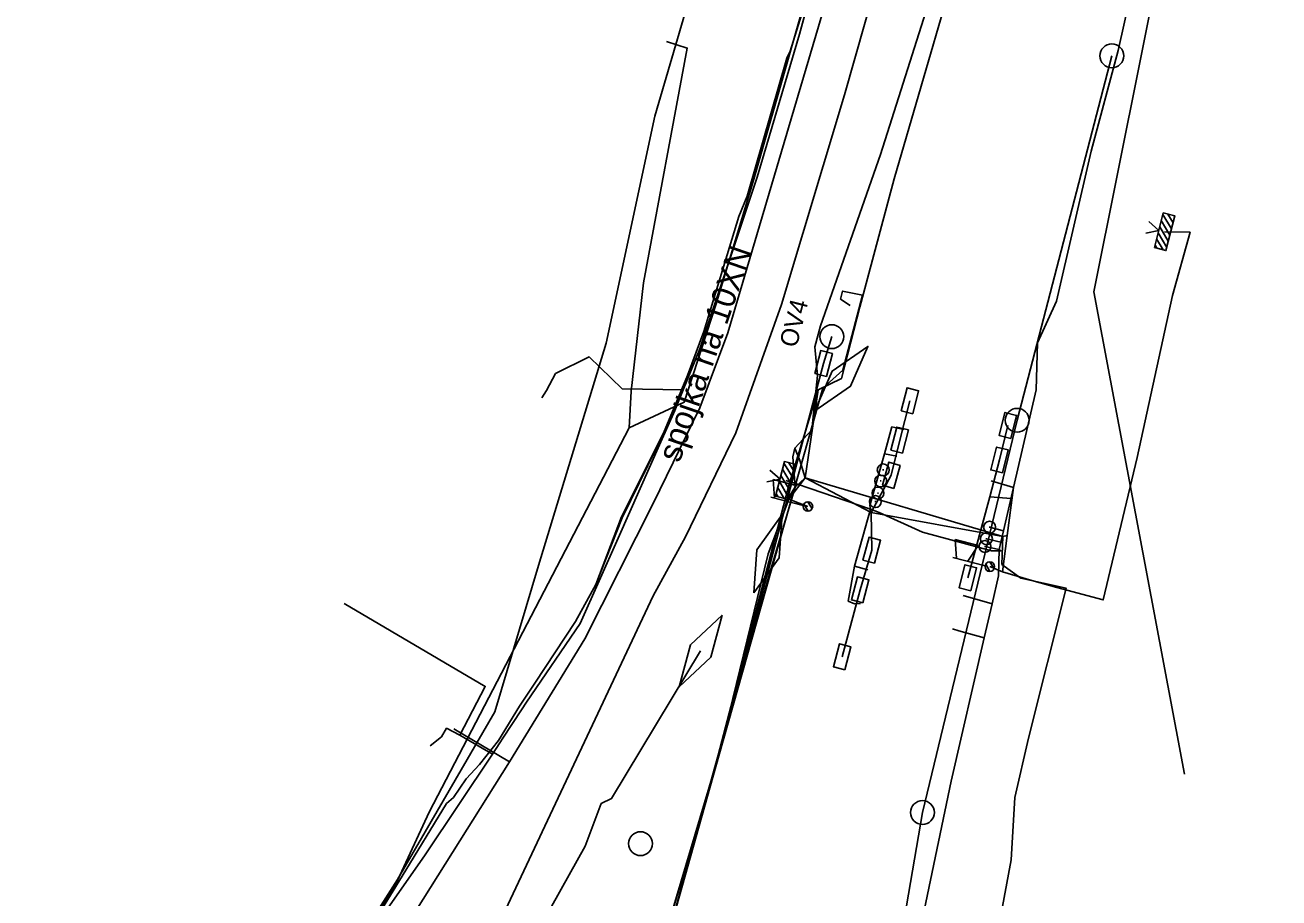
# Model space of a CAD drawing. Extents: x -748507 to -687366, y -1057342 to -1024924.
# Drawn here: x -743353.8 to -743248.5, y -1034654.5 to -1034581.2 of the extents above; entities that cross this region are included whole.
import ezdxf

# ---------------------------------------------------------------- set-up
doc = ezdxf.new("R2010")
doc.units = 0
for name, color, linetype in [('6kV - SŽDC', 7, 'Continuous'), ('DK + TKK - SŽDC', 7, 'Continuous'), ('kanalizace ČD', 7, 'Continuous'), ('PRE - NN', 7, 'Continuous'), ('PRE - OK', 7, 'Continuous'), ('PRE - VN', 7, 'Continuous'), ('Sděl MK - SŽDC', 7, 'Continuous'), ('STL - PRAŽSKÁ PLYNÁRENSKÁ', 7, 'Continuous'), ('Telefonica O2', 7, 'Continuous'), ('TK+DOK_Pha Holešovice - Kralupy', 7, 'Continuous'), ('Vedení NN - SŽDC', 7, 'Continuous')]:
    doc.layers.add(name, color=color, linetype=linetype)

msp = doc.modelspace()

# ---------------------------------------------------------------- linework, layer by layer
at = {"layer": '6kV - SŽDC'}
for points in [[(-743295.26, -1034630.77), (-743296.21, -1034634.29), (-743298.88, -1034636.77), (-743297.93, -1034633.25), (-743295.26, -1034630.77)], [(-743297.07, -1034633.77), (-743304.54, -1034646.16), (-743305.41, -1034646.57), (-743306.77, -1034650.16), (-743310.94, -1034657.62), (-743310.76, -1034659.86), (-743313.4, -1034662.22), (-743314.46, -1034662.46), (-743323.73, -1034678.74), (-743332.19, -1034693.38), (-743337.55, -1034703.39), (-743340.58, -1034715.43), (-743341.14, -1034718.66)]]:
    msp.add_lwpolyline(points, dxfattribs=at)
at = {"layer": 'DK + TKK - SŽDC'}
for p, q in [((-743289.34, -1034619.22), (-743290.07, -1034618.01)), ((-743289.21, -1034618.71), (-743289.65, -1034617.98)), ((-743289.08, -1034618.2), (-743289.13, -1034618.11)), ((-743289.61, -1034620.25), (-743290.33, -1034619.04)), ((-743289.47, -1034619.74), (-743290.2, -1034618.52)), ((-743282, -1034619.5), (-743281.9, -1034619.5)), ((-743281.79, -1034618.57), (-743281.69, -1034618.57)), ((-743290.05, -1034620.97), (-743290.59, -1034620.07)), ((-743289.74, -1034620.77), (-743290.46, -1034619.55)), ((-743282.23, -1034620.52), (-743282.13, -1034620.52)), ((-743290.57, -1034620.84), (-743290.72, -1034620.58)), ((-743282.45, -1034621.23), (-743282.35, -1034621.23)), ((-743272.86, -1034623.38), (-743272.76, -1034623.38)), ((-743273.13, -1034624.35), (-743273.03, -1034624.35)), ((-743273.25, -1034625), (-743273.15, -1034625))]:
    msp.add_line(p, q, dxfattribs=at)
for points in [[(-743285.25, -1034610.91), (-743283.7, -1034604.91), (-743280.81, -1034594.13), (-743276.29, -1034578.55), (-743273.28, -1034568.35), (-743270.77, -1034566.1), (-743268.13, -1034563.75), (-743265.78, -1034554.28)], [(-743262.02, -1034583.38), (-743259.96, -1034574.09), (-743257.39, -1034564.51)], [(-743268.89, -1034611.84), (-743268.78, -1034607.9), (-743267.19, -1034604.4), (-743264.3, -1034591.83), (-743262.02, -1034583.38)], [(-743295.6, -1034642.52), (-743289.66, -1034619.88), (-743287.21, -1034611.85), (-743285.25, -1034610.91)], [(-743270.8, -1034620.05), (-743268.89, -1034611.84)], [(-743271.04, -1034615.93), (-743272.01, -1034615.68), (-743271.52, -1034613.75), (-743270.55, -1034614), (-743271.04, -1034615.93)], [(-743281.63, -1034617.23), (-743281.01, -1034614.96)], [(-743281.01, -1034614.96), (-743280.01, -1034615.18)], [(-743272.79, -1034620.84), (-743271.98, -1034617.74), (-743271.28, -1034614.84)], [(-743282.8, -1034621.87), (-743282.87, -1034621.55), (-743281.63, -1034617.23), (-743280.59, -1034617.42)], [(-743271.74, -1034618.83), (-743272.71, -1034618.58), (-743272.22, -1034616.65), (-743271.25, -1034616.9), (-743271.74, -1034618.83)], [(-743290.78, -1034620.79), (-743290.03, -1034617.88), (-743289.06, -1034618.13), (-743289.81, -1034621.04), (-743290.78, -1034620.79)], [(-743291.5, -1034619.57), (-743290.4, -1034619.34), (-743291.25, -1034618.6)], [(-743289.09, -1034619.71), (-743289.92, -1034619.46)], [(-743288.28, -1034619.23), (-743271.7, -1034624.16)], [(-743270.8, -1034620.05), (-743272.67, -1034619.48)], [(-743282.8, -1034621.87), (-743286.9, -1034620.46), (-743287.78, -1034620.15), (-743289.09, -1034619.71)], [(-743272.6, -1034629.81), (-743272.06, -1034627.47), (-743272.01, -1034625.24), (-743271.87, -1034624.63), (-743271.65, -1034623.68), (-743270.8, -1034620.05)], [(-743274.64, -1034627.62), (-743272.79, -1034620.84), (-743270.99, -1034620.96)], [(-743282.8, -1034621.87), (-743284.14, -1034626.65), (-743283.02, -1034626.97)], [(-743278.43, -1034623.8), (-743282.08, -1034622.14), (-743282.8, -1034621.87)], [(-743271.65, -1034623.68), (-743272.81, -1034623.38)], [(-743272.01, -1034625.24), (-743271.86, -1034625.36), (-743272.64, -1034625.36), (-743278.43, -1034623.8)], [(-743271.87, -1034624.63), (-743273.08, -1034624.35)], [(-743272.01, -1034625.24), (-743273.2, -1034625)], [(-743284.14, -1034626.65), (-743284.69, -1034629.6)], [(-743274.4, -1034628.71), (-743275.37, -1034628.46), (-743274.88, -1034626.53), (-743273.91, -1034626.78), (-743274.4, -1034628.71)], [(-743284.69, -1034629.6), (-743284.16, -1034629.8), (-743283.64, -1034629.79)], [(-743273.26, -1034632.66), (-743272.6, -1034629.81), (-743275.04, -1034629.11)], [(-743276.03, -1034644.69), (-743273.26, -1034632.66), (-743275.38, -1034632.08), (-743275.92, -1034631.92)], [(-743315.44, -1034713.05), (-743314.23, -1034708.71), (-743313.63, -1034706.6), (-743302.64, -1034667.85), (-743295.6, -1034642.52)], [(-743287.3, -1034726.01), (-743282.01, -1034701.16), (-743281.85, -1034698.52), (-743280.62, -1034695.37), (-743278.88, -1034691.73), (-743277.32, -1034684.93), (-743277.88, -1034683.89), (-743280.38, -1034683), (-743283.09, -1034682.28), (-743283.91, -1034682.14), (-743283.65, -1034681.11), (-743283.36, -1034679.73), (-743281.64, -1034671.49), (-743276.03, -1034644.69)]]:
    msp.add_lwpolyline(points, dxfattribs=at)
msp.add_lwpolyline([(-743290.78, -1034620.79), (-743290.03, -1034617.88), (-743289.06, -1034618.13), (-743289.81, -1034621.04)], close=True, dxfattribs=at)
for centre in [(-743281.74, -1034618.57), (-743281.95, -1034619.5), (-743282.18, -1034620.52), (-743282.4, -1034621.23), (-743272.81, -1034623.38), (-743273.2, -1034625), (-743273.08, -1034624.35)]:
    msp.add_circle(centre, 0.5, dxfattribs=at)
at = {"layer": 'kanalizace ČD'}
msp.add_lwpolyline([(-743262.55, -1034583.82), (-743270.5, -1034614.41), (-743278.45, -1034647.33), (-743284.53, -1034682.91), (-743290.75, -1034695.35)], dxfattribs=at)
for centre in [(-743262.55, -1034583.82), (-743270.5, -1034614.41), (-743278.45, -1034647.33), (-743302.11, -1034649.94)]:
    msp.add_circle(centre, 1, dxfattribs=at)
at = {"layer": 'PRE - NN'}
for points in [[(-743303.07, -1034615.04), (-743298.46, -1034612.89), (-743295.78, -1034604.72), (-743292.59, -1034594.17), (-743286.55, -1034573.02), (-743286.07, -1034571.35), (-743285.82, -1034570.59), (-743284.5, -1034566.54)], [(-743299.92, -1034582.63), (-743298.19, -1034583.17), (-743301.86, -1034602.86), (-743302.89, -1034611.97), (-743303.07, -1034615.04)], [(-743373.22, -1034733.88), (-743372.79, -1034733.31), (-743370.86, -1034730.74), (-743367.71, -1034726.54), (-743355.34, -1034708.17), (-743347.28, -1034694.56), (-743327.35, -1034660.91), (-743322.5, -1034653.04), (-743319.86, -1034647.3), (-743303.07, -1034615.04)]]:
    msp.add_lwpolyline(points, dxfattribs=at)
at = {"layer": 'PRE - OK'}
msp.add_lwpolyline([(-743288.46, -1034579.93), (-743289.54, -1034583.42), (-743289.84, -1034584.01), (-743293.17, -1034595.6), (-743293.86, -1034597.31), (-743296.8, -1034606.96), (-743298.18, -1034610.66), (-743300.17, -1034615.5), (-743303.71, -1034622.52), (-743305.85, -1034628.2), (-743307.57, -1034631.3), (-743310.99, -1034636.48), (-743312.27, -1034638.4), (-743314.04, -1034641.28), (-743315.62, -1034643.29), (-743316.76, -1034644.49), (-743317.81, -1034646.06), (-743318.39, -1034646.57), (-743322.13, -1034652.67), (-743326.9, -1034660.33)], dxfattribs=at)
at = {"layer": 'PRE - VN'}
msp.add_lwpolyline([(-743326.78, -1034660.27), (-743322.13, -1034652.67), (-743318.39, -1034646.57), (-743317.81, -1034646.06), (-743316.76, -1034644.49), (-743315.62, -1034643.29), (-743314.04, -1034641.28), (-743312.27, -1034638.4), (-743310.99, -1034636.48), (-743307.57, -1034631.3), (-743305.85, -1034628.2), (-743303.65, -1034622.6), (-743300.06, -1034615.3), (-743298.18, -1034610.66), (-743296.8, -1034606.96), (-743293.86, -1034597.31), (-743293.17, -1034595.6), (-743289.84, -1034584.01), (-743289.54, -1034583.42), (-743288.46, -1034579.93)], dxfattribs=at)
at = {"layer": 'Sděl MK - SŽDC'}
for p, q in [((-743257.54, -1034598.35), (-743258.26, -1034597.14)), ((-743257.41, -1034597.84), (-743257.84, -1034597.11)), ((-743257.28, -1034597.33), (-743257.33, -1034597.24)), ((-743257.81, -1034599.38), (-743258.53, -1034598.17)), ((-743257.68, -1034598.87), (-743258.4, -1034597.65)), ((-743258.25, -1034600.1), (-743258.79, -1034599.19)), ((-743257.94, -1034599.9), (-743258.66, -1034598.68)), ((-743258.77, -1034599.97), (-743258.92, -1034599.71)), ((-743290.87, -1034620.95), (-743290.98, -1034619.37)), ((-743290.98, -1034619.37), (-743289.05, -1034619.87)), ((-743289.05, -1034619.87), (-743289.9, -1034621.2)), ((-743291.16, -1034620.87), (-743288.45, -1034621.56)), ((-743288.05, -1034622.04), (-743288.4, -1034621.44)), ((-743287.71, -1034621.83), (-743288.06, -1034621.24)), ((-743275.6, -1034626), (-743275.71, -1034624.42)), ((-743275.71, -1034624.42), (-743273.78, -1034624.92)), ((-743273.78, -1034624.92), (-743274.63, -1034626.24)), ((-743275.89, -1034625.92), (-743273.18, -1034626.61)), ((-743272.78, -1034627.09), (-743273.13, -1034626.49)), ((-743272.44, -1034626.88), (-743272.79, -1034626.29))]:
    msp.add_line(p, q, dxfattribs=at)
for points in [[(-743268.89, -1034611.84), (-743268.78, -1034607.9), (-743267.19, -1034604.4), (-743264.3, -1034591.83), (-743262.02, -1034583.38), (-743259.96, -1034574.09), (-743257.39, -1034564.51), (-743253.16, -1034548.54), (-743252.58, -1034546.35), (-743251.82, -1034543.49), (-743251.53, -1034542.4), (-743246.18, -1034521.96), (-743246.2, -1034521.46), (-743241.03, -1034504.8)], [(-743288.28, -1034619.23), (-743287.21, -1034611.85), (-743285.25, -1034610.91), (-743283.7, -1034604.91), (-743280.81, -1034594.13), (-743276.29, -1034578.55), (-743273.28, -1034568.35), (-743270.77, -1034566.1), (-743268.13, -1034563.75), (-743265.78, -1034554.28), (-743263.76, -1034546.18), (-743263.12, -1034543.58), (-743262.06, -1034539.33), (-743261.91, -1034538.73), (-743261.84, -1034538.46), (-743260.73, -1034534.41)], [(-743258.98, -1034599.92), (-743258.23, -1034597.01), (-743257.26, -1034597.26), (-743258.01, -1034600.17), (-743258.98, -1034599.92)], [(-743259.7, -1034598.7), (-743258.6, -1034598.47), (-743259.45, -1034597.73)], [(-743271.72, -1034627.13), (-743269.28, -1034627.85), (-743267.16, -1034628.45), (-743263.27, -1034629.49), (-743260.42, -1034617.53), (-743257.46, -1034603.94), (-743255.99, -1034598.63), (-743258.12, -1034598.59)], [(-743352.91, -1034869.19), (-743345.75, -1034839.63), (-743335.08, -1034793.5), (-743334.25, -1034789.71), (-743332.49, -1034782.2), (-743325.48, -1034752.28), (-743315.44, -1034713.05), (-743314.23, -1034708.71), (-743302.64, -1034667.85), (-743295.54, -1034642.57), (-743291.41, -1034625.61), (-743289.65, -1034621.03), (-743288.28, -1034619.23), (-743271.7, -1034624.16), (-743271.33, -1034624.08), (-743270.8, -1034620.05), (-743268.89, -1034611.84)], [(-743289.65, -1034621.03), (-743288.06, -1034621.64)], [(-743292.6, -1034628.9), (-743292.35, -1034625.27), (-743290.22, -1034622.32), (-743290.47, -1034625.95), (-743292.6, -1034628.9)], [(-743271.33, -1034624.08), (-743271.72, -1034627.13), (-743272.79, -1034626.69)]]:
    msp.add_lwpolyline(points, dxfattribs=at)
msp.add_lwpolyline([(-743258.98, -1034599.92), (-743258.23, -1034597.01), (-743257.26, -1034597.26), (-743258.01, -1034600.17)], close=True, dxfattribs=at)
for centre in [(-743288.06, -1034621.64), (-743288.06, -1034621.64), (-743272.79, -1034626.69), (-743272.79, -1034626.69)]:
    msp.add_circle(centre, 0.401, dxfattribs=at)
at = {"layer": 'STL - PRAŽSKÁ PLYNÁRENSKÁ'}
msp.add_line((-743313.1, -1034643.06), (-743317.79, -1034640.29), dxfattribs=at)
msp.add_lwpolyline([(-743280.99, -1034562.96), (-743284.39, -1034571.91), (-743284.75, -1034573.11), (-743294.77, -1034607.06), (-743297.13, -1034613.36), (-743301.04, -1034621.39), (-743306.79, -1034632.74), (-743313.1, -1034643.06), (-743327, -1034665.14), (-743349, -1034699.17), (-743354.62, -1034707.84), (-743364.17, -1034722.22), (-743370.88, -1034733.31), (-743371.96, -1034734.74), (-743373.77, -1034737.08), (-743377.3, -1034739.58), (-743378.17, -1034740.1), (-743383.37, -1034743.1), (-743383.84, -1034743.37)], dxfattribs=at)
at = {"layer": 'Telefonica O2'}
for points in [[(-743298.52, -1034611.85), (-743297.14, -1034608.42), (-743292.31, -1034594), (-743288.76, -1034582.01), (-743285.45, -1034569.81), (-743282.5, -1034560.98), (-743280.57, -1034554.9), (-743279.87, -1034553.62), (-743278.41, -1034552.86), (-743277.85, -1034553.06), (-743273.53, -1034554.65), (-743273.04, -1034554.83)], [(-743237.34, -1034587.18), (-743246.67, -1034567.23), (-743248.26, -1034565.84), (-743251.53, -1034564.06), (-743255.45, -1034563.21), (-743258.18, -1034563.91), (-743268.61, -1034561.37), (-743270.89, -1034561.08), (-743274.61, -1034562.22), (-743276.9, -1034563.81), (-743278.44, -1034565.45), (-743279.78, -1034568.77), (-743284.99, -1034587.1), (-743290.28, -1034604.7), (-743294.12, -1034615.45), (-743298.34, -1034624.19), (-743301.04, -1034629.14), (-743314.56, -1034657.86), (-743319.49, -1034663.3), (-743319.01, -1034664.96), (-743320.86, -1034665.49), (-743329.4, -1034675.81), (-743343.26, -1034696.57), (-743359.5, -1034716.04)], [(-743296.48, -1034569.26), (-743269.82, -1034561.4), (-743256.14, -1034564.14), (-743264.05, -1034603.62), (-743256.46, -1034644.12)], [(-743327.41, -1034660.65), (-743322.5, -1034652.96), (-743314.35, -1034638.88), (-743310.68, -1034626.6), (-743304.99, -1034607.94), (-743300.92, -1034588.88), (-743295.34, -1034569.86)], [(-743298.52, -1034611.85), (-743303.64, -1034611.78), (-743306.43, -1034609.09), (-743309.24, -1034610.49), (-743309.99, -1034611.9), (-743310.39, -1034612.52)], [(-743314.55, -1034642.44), (-743313.92, -1034641.47), (-743313.67, -1034641.09), (-743312.11, -1034638.7), (-743311.69, -1034638.06), (-743307.19, -1034631.45), (-743304, -1034624.29), (-743300.4, -1034616.22), (-743299.22, -1034613.58), (-743298.52, -1034611.85)], [(-743300.4, -1034616.22), (-743304, -1034624.29)], [(-743317.28, -1034640.84), (-743315.15, -1034636.74), (-743326.99, -1034629.78)], [(-743312.11, -1034638.7), (-743313.67, -1034641.09), (-743313.92, -1034641.47)], [(-743317.28, -1034640.84), (-743318.39, -1034640.26), (-743318.83, -1034640.97), (-743319.78, -1034641.74)], [(-743317.28, -1034640.84), (-743314.55, -1034642.44)], [(-743314.55, -1034642.44), (-743320.2, -1034650.89), (-743327.55, -1034661.4)]]:
    msp.add_lwpolyline(points, dxfattribs=at)
at = {"layer": 'TK+DOK_Pha Holešovice - Kralupy'}
for points in [[(-743295.6, -1034642.52), (-743289.66, -1034619.88), (-743287.21, -1034611.85), (-743285.25, -1034610.91), (-743283.7, -1034604.91), (-743280.81, -1034594.13), (-743276.29, -1034578.55), (-743273.28, -1034568.35), (-743270.77, -1034566.1), (-743268.13, -1034563.75), (-743265.78, -1034554.28), (-743263.76, -1034546.18), (-743263.12, -1034543.58), (-743261.91, -1034538.73), (-743256.18, -1034517.29), (-743251.9, -1034501.61)], [(-743285.25, -1034610.91), (-743283.7, -1034604.91), (-743280.81, -1034594.13), (-743276.29, -1034578.55), (-743273.28, -1034568.35), (-743270.77, -1034566.1), (-743268.13, -1034563.75), (-743265.78, -1034554.28), (-743263.76, -1034546.18), (-743263.12, -1034543.58), (-743261.91, -1034538.73), (-743256.18, -1034517.29), (-743251.9, -1034501.61)], [(-743287.47, -1034613.61), (-743286.02, -1034610.28), (-743283.03, -1034608.21), (-743284.48, -1034611.55), (-743287.47, -1034613.61)], [(-743348.28, -1034838.87), (-743345.94, -1034839.57), (-743334.25, -1034789.71), (-743332.49, -1034782.2), (-743315.44, -1034713.05), (-743314.23, -1034708.71), (-743313.63, -1034706.6), (-743302.64, -1034667.85), (-743295.6, -1034642.52), (-743289.66, -1034619.88), (-743287.21, -1034611.85), (-743285.25, -1034610.91)], [(-743345.94, -1034839.57), (-743335.08, -1034793.5), (-743334.25, -1034789.71), (-743332.49, -1034782.2), (-743315.44, -1034713.05), (-743314.23, -1034708.71), (-743313.63, -1034706.6), (-743302.64, -1034667.85), (-743295.6, -1034642.52)]]:
    msp.add_lwpolyline(points, dxfattribs=at)
at = {"layer": 'Vedení NN - SŽDC'}
for points in [[(-743287.72, -1034615.2), (-743287.27, -1034610.65), (-743287.49, -1034608.23), (-743287, -1034606.47), (-743281.98, -1034592.1), (-743277.42, -1034577.71), (-743275.17, -1034569.4), (-743274.39, -1034567.83), (-743272.45, -1034566.38), (-743268.12, -1034563.65), (-743266.28, -1034555.99), (-743263.15, -1034542.48), (-743262.87, -1034541.41), (-743253.71, -1034543.75), (-743253.26, -1034544.78), (-743253.96, -1034547.73), (-743254.88, -1034550.96)], [(-743305.35, -1034675.45), (-743295.55, -1034642.56), (-743286.8, -1034611.71), (-743285.13, -1034610.19), (-743283.47, -1034603.9), (-743285.15, -1034603.57), (-743285.32, -1034604.23), (-743284.52, -1034604.77)], [(-743352.92, -1034869.25), (-743345.75, -1034839.63), (-743335.08, -1034793.5), (-743315.44, -1034713.05), (-743305.35, -1034675.45), (-743295.56, -1034642.57), (-743295.29, -1034641.55), (-743291.69, -1034628.1), (-743286.74, -1034609.65), (-743286.05, -1034607.39)], [(-743286.5, -1034610.74), (-743287.47, -1034610.49), (-743286.98, -1034608.56), (-743286.01, -1034608.81), (-743286.5, -1034610.74)], [(-743279.26, -1034613.86), (-743280.23, -1034613.61), (-743279.74, -1034611.68), (-743278.77, -1034611.93), (-743279.26, -1034613.86)], [(-743285.18, -1034634.25), (-743283.67, -1034628.64), (-743282.7, -1034625.31), (-743282.74, -1034622.16), (-743281.06, -1034619.02), (-743280.36, -1034616.07), (-743279.5, -1034612.77)], [(-743295.54, -1034642.57), (-743293.94, -1034636.83), (-743291.29, -1034627.29), (-743289.14, -1034620.01), (-743288.28, -1034619.23), (-743288.75, -1034617.78), (-743289.17, -1034616.74), (-743287.72, -1034615.2)], [(-743280.12, -1034617.16), (-743281.09, -1034616.92), (-743280.6, -1034614.98), (-743279.63, -1034615.22), (-743280.12, -1034617.16)], [(-743289.14, -1034620.01), (-743289.34, -1034617.48), (-743289.17, -1034616.74)], [(-743280.84, -1034620.12), (-743281.8, -1034619.85), (-743281.28, -1034617.92), (-743280.32, -1034618.19), (-743280.84, -1034620.12)], [(-743288.28, -1034619.23), (-743282.74, -1034622.16), (-743271.7, -1034624.16), (-743271.78, -1034626.51), (-743270.19, -1034627.66), (-743266.38, -1034628.5), (-743269.56, -1034641.1), (-743270.7, -1034646.06), (-743271.01, -1034651.3), (-743273.99, -1034667.4), (-743275.8, -1034679.02), (-743278.71, -1034692.05), (-743279.7, -1034693.38), (-743280.68, -1034696.43), (-743280.25, -1034699.02), (-743281.48, -1034701.17), (-743283.39, -1034708.73), (-743288.22, -1034730.7)], [(-743282.47, -1034626.4), (-743283.44, -1034626.15), (-743282.93, -1034624.22), (-743281.96, -1034624.47), (-743282.47, -1034626.4)], [(-743283.44, -1034629.73), (-743284.41, -1034629.48), (-743283.9, -1034627.55), (-743282.94, -1034627.8), (-743283.44, -1034629.73)], [(-743284.95, -1034635.34), (-743285.92, -1034635.09), (-743285.41, -1034633.16), (-743284.45, -1034633.41), (-743284.95, -1034635.34)], [(-743335.08, -1034793.5), (-743315.44, -1034713.05), (-743295.54, -1034642.57)]]:
    msp.add_lwpolyline(points, dxfattribs=at)
msp.add_circle((-743286.05, -1034607.39), 1, dxfattribs=at)

# ---------------------------------------------------------------- texts
at = {"layer": 'TK+DOK_Pha Holešovice - Kralupy'}
msp.add_text('spojka na 10XN', height=2, rotation=71.0643, dxfattribs=at).set_placement((-743298.84, -1034618.04))
at = {"layer": 'Vedení NN - SŽDC'}
msp.add_text('OV4', height=1.5, rotation=75.6534, dxfattribs=at).set_placement((-743289.02, -1034608.38))

doc.saveas('drawing.dxf')
